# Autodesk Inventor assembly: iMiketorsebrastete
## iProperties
Company: Cross Bros.
Shininess: 64.0
Length Units: 11272
Angle Units: 11279
Time Units: 11290
Mass Units: 11286
Length Display Precision: 3
Angle Display Precision: 2
Compacted: True
Part Number: iMiketorsebrastete
Document SubType Name: Assembly
Created: 2003-03
Designer: MVF
Catalog Web Link: www.crossbros.com
Density: 0.0
Volumn: 0.0
Area: 0.0
PropertySet Name: Model Information
Control State: 0
Master: False
Checked Out: False
Author: MVF
Title: iMike
